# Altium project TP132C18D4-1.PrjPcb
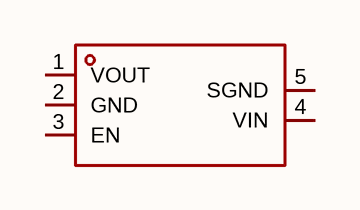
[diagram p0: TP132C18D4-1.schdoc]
1 sheet, 1 parts. Net scope: global (net labels, ports and power ports of the same name join across sheets).

## Sheet TP132C18D4-1.schdoc
size 127 x 101 mm

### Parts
U?  tp132c18d4-1  [DFN-4_L1.0-W1.0-P0.65-BL-EP]  (value not drawn)

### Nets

Not connected (* = marked no-connect by the designer): U? 1(VOUT) 2(GND) 3(EN) 4(VIN) 5(SGND)

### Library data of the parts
U? = tp132c18d4-1: 输出极性:正极;工作电压:5.5V;输出电压:1.8V;输出电流:300mA;电源纹波抑制比(PSRR):78dB@(100Hz);输出类型:固定;; Manufacturer: TECH PUBLIC(台舟); AddInBom: yes; ModelId: bb5c60478e114cecafb4cacfcccae5cc; ModelName: DFN-4_L1.0-W1.0-H0.5-P0.65-BL-EP; ModelTransform: 40.1574,40.1574,0,0,0,0,0.18,0.02,0; Output Configuration: 正极; Voltage - Supply: 5.5V; Output Voltage: 1.8V; Output Current: 300mA; Voltage Dropout: 280mV@(300mA); standby current: 2uA; Output Type: 固定; Number of Outputs: 1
